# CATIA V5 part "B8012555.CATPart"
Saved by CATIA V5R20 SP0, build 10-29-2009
Part number: B8012555
Revision: 6
Definition: design
Nomenclature: B8012555
Source: made
Description: NOT SPECIFIED
Bounding box of the stored display mesh (mm): x -22.5 to 22.5, y -22.5 to 22.5, z 0 to 55
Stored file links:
  C:\Users\Utente\Desktop\3D files B801\B8012555.CATPart
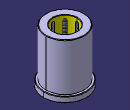
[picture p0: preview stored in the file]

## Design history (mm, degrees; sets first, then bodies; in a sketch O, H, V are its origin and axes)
Body1 "MANIFOLD_SOLID_BREP #38" (main body)
  Solid1: solid without history
Body2 "MANIFOLD_SOLID_BREP #76"
  Solid2: solid without history
Body3 "MANIFOLD_SOLID_BREP #114"
  Solid3: solid without history
Body4 "MANIFOLD_SOLID_BREP #152"
  Solid4: solid without history
Body5 "MANIFOLD_SOLID_BREP #190"
  Solid5: solid without history
Body6 "MANIFOLD_SOLID_BREP #228"
  Solid6: solid without history
Body7 "MANIFOLD_SOLID_BREP #266"
  Solid7: solid without history
Body8 "MANIFOLD_SOLID_BREP #304"
  Solid8: solid without history
Body9 "MANIFOLD_SOLID_BREP #342"
  Solid9: solid without history
Body10 "MANIFOLD_SOLID_BREP #2276"
  Solid10: solid without history
Body11 "MANIFOLD_SOLID_BREP #2314"
  Solid11: solid without history
Body12 "MANIFOLD_SOLID_BREP #2352"
  Solid12: solid without history
Body13 "MANIFOLD_SOLID_BREP #2390"
  Solid13: solid without history
Body14 "MANIFOLD_SOLID_BREP #2428"
  Solid14: solid without history
Body15 "MANIFOLD_SOLID_BREP #2466"
  Solid15: solid without history
Body16 "MANIFOLD_SOLID_BREP #2504"
  Solid16: solid without history
Body17 "MANIFOLD_SOLID_BREP #2542"
  Solid17: solid without history
Body18 "MANIFOLD_SOLID_BREP #2580"
  Solid18: solid without history
Body19 "MANIFOLD_SOLID_BREP #2618"
  Solid19: solid without history
Body20 "MANIFOLD_SOLID_BREP #2656"
  Solid20: solid without history
Body21 "MANIFOLD_SOLID_BREP #2694"
  Solid21: solid without history
Body22 "MANIFOLD_SOLID_BREP #2732"
  Solid22: solid without history
Body23 "MANIFOLD_SOLID_BREP #2770"
  Solid23: solid without history
Body24 "MANIFOLD_SOLID_BREP #2808"
  Solid24: solid without history
Body25 "MANIFOLD_SOLID_BREP #2846"
  Solid25: solid without history
Body26 "MANIFOLD_SOLID_BREP #2884"
  Solid26: solid without history
Body27 "MANIFOLD_SOLID_BREP #2922"
  Solid27: solid without history
Body28 "MANIFOLD_SOLID_BREP #2960"
  Solid28: solid without history
Body29 "MANIFOLD_SOLID_BREP #2998"
  Solid29: solid without history
Body30 "MANIFOLD_SOLID_BREP #3036"
  Solid30: solid without history
Body31 "MANIFOLD_SOLID_BREP #3074"
  Solid31: solid without history
Body32 "MANIFOLD_SOLID_BREP #3112"
  Solid32: solid without history
Body33 "MANIFOLD_SOLID_BREP #3150"
  Solid33: solid without history
Body34 "MANIFOLD_SOLID_BREP #3188"
  Solid34: solid without history
Body35 "MANIFOLD_SOLID_BREP #3226"
  Solid35: solid without history
Body36 "MANIFOLD_SOLID_BREP #3264"
  Solid36: solid without history
Body37 "MANIFOLD_SOLID_BREP #3302"
  Solid37: solid without history
Body38 "MANIFOLD_SOLID_BREP #3340"
  Solid38: solid without history
Body39 "MANIFOLD_SOLID_BREP #3378"
  Solid39: solid without history
Body40 "MANIFOLD_SOLID_BREP #3416"
  Solid40: solid without history
Body41 "MANIFOLD_SOLID_BREP #3454"
  Solid41: solid without history
Body42 "MANIFOLD_SOLID_BREP #3492"
  Solid42: solid without history
Body43 "MANIFOLD_SOLID_BREP #3530"
  Solid43: solid without history
Body44 "MANIFOLD_SOLID_BREP #3568"
  Solid44: solid without history
Body45 "MANIFOLD_SOLID_BREP #3606"
  Solid45: solid without history
Body46 "MANIFOLD_SOLID_BREP #3644"
  Solid46: solid without history
Body47 "MANIFOLD_SOLID_BREP #3682"
  Solid47: solid without history
Body48 "MANIFOLD_SOLID_BREP #3720"
  Solid48: solid without history
Body49 "MANIFOLD_SOLID_BREP #3758"
  Solid49: solid without history
Body50 "MANIFOLD_SOLID_BREP #3796"
  Solid50: solid without history
Body51 "MANIFOLD_SOLID_BREP #3834"
  Solid51: solid without history
Body52 "MANIFOLD_SOLID_BREP #3872"
  Solid52: solid without history
Body53 "MANIFOLD_SOLID_BREP #3910"
  Solid53: solid without history
Body54 "MANIFOLD_SOLID_BREP #3948"
  Solid54: solid without history
Body55 "MANIFOLD_SOLID_BREP #3986"
  Solid55: solid without history
Body56 "MANIFOLD_SOLID_BREP #4024"
  Solid56: solid without history
Body57 "MANIFOLD_SOLID_BREP #4062"
  Solid57: solid without history
Body58 "MANIFOLD_SOLID_BREP #4100"
  Solid58: solid without history
Body59 "MANIFOLD_SOLID_BREP #4138"
  Solid59: solid without history
Body60 "MANIFOLD_SOLID_BREP #4176"
  Solid60: solid without history
Body61 "MANIFOLD_SOLID_BREP #4214"
  Solid61: solid without history
Body62 "MANIFOLD_SOLID_BREP #4252"
  Solid62: solid without history
Body63 "MANIFOLD_SOLID_BREP #4290"
  Solid63: solid without history
Body64 "MANIFOLD_SOLID_BREP #4328"
  Solid64: solid without history
Body65 "MANIFOLD_SOLID_BREP #4366"
  Solid65: solid without history
Body66 "MANIFOLD_SOLID_BREP #4404"
  Solid66: solid without history
Body67 "MANIFOLD_SOLID_BREP #4442"
  Solid67: solid without history
Body68 "MANIFOLD_SOLID_BREP #4480"
  Solid68: solid without history
Body69 "MANIFOLD_SOLID_BREP #4518"
  Solid69: solid without history
Body70 "MANIFOLD_SOLID_BREP #4556"
  Solid70: solid without history
Body71 "MANIFOLD_SOLID_BREP #4594"
  Solid71: solid without history
Body72 "MANIFOLD_SOLID_BREP #4632"
  Solid72: solid without history
Body73 "MANIFOLD_SOLID_BREP #4670"
  Solid73: solid without history
Body74 "MANIFOLD_SOLID_BREP #4708"
  Solid74: solid without history
Body75 "MANIFOLD_SOLID_BREP #4746"
  Solid75: solid without history
Body76 "MANIFOLD_SOLID_BREP #4784"
  Solid76: solid without history
Body77 "MANIFOLD_SOLID_BREP #4822"
  Solid77: solid without history
Body78 "MANIFOLD_SOLID_BREP #4860"
  Solid78: solid without history
Body79 "MANIFOLD_SOLID_BREP #4898"
  Solid79: solid without history
Body80 "MANIFOLD_SOLID_BREP #4936"
  Solid80: solid without history
Body81 "MANIFOLD_SOLID_BREP #4974"
  Solid81: solid without history
Body82 "MANIFOLD_SOLID_BREP #5012"
  Solid82: solid without history
Body83 "MANIFOLD_SOLID_BREP #5050"
  Solid83: solid without history
Body84 "MANIFOLD_SOLID_BREP #5088"
  Solid84: solid without history
Body85 "MANIFOLD_SOLID_BREP #5126"
  Solid85: solid without history
Body86 "MANIFOLD_SOLID_BREP #5164"
  Solid86: solid without history
Body87 "MANIFOLD_SOLID_BREP #5202"
  Solid87: solid without history
Body88 "MANIFOLD_SOLID_BREP #5240"
  Solid88: solid without history
Body89 "MANIFOLD_SOLID_BREP #5278"
  Solid89: solid without history
Body90 "MANIFOLD_SOLID_BREP #5316"
  Solid90: solid without history
Body91 "MANIFOLD_SOLID_BREP #5354"
  Solid91: solid without history
Body92 "MANIFOLD_SOLID_BREP #5392"
  Solid92: solid without history
Body93 "MANIFOLD_SOLID_BREP #5430"
  Solid93: solid without history
Body94 "MANIFOLD_SOLID_BREP #5468"
  Solid94: solid without history
Body95 "MANIFOLD_SOLID_BREP #5506"
  Solid95: solid without history
Body96 "MANIFOLD_SOLID_BREP #5544"
  Solid96: solid without history
Body97 "MANIFOLD_SOLID_BREP #5582"
  Solid97: solid without history
Body98 "MANIFOLD_SOLID_BREP #5620"
  Solid98: solid without history
Body99 "MANIFOLD_SOLID_BREP #5658"
  Solid99: solid without history
Body100 "MANIFOLD_SOLID_BREP #5696"
  Solid100: solid without history
Body101 "MANIFOLD_SOLID_BREP #5734"
  Solid101: solid without history
Body102 "MANIFOLD_SOLID_BREP #5772"
  Solid102: solid without history
Body103 "MANIFOLD_SOLID_BREP #5810"
  Solid103: solid without history
Body104 "MANIFOLD_SOLID_BREP #5848"
  Solid104: solid without history
Body105 "MANIFOLD_SOLID_BREP #5886"
  Solid105: solid without history
Body106 "MANIFOLD_SOLID_BREP #5924"
  Solid106: solid without history
Body107 "MANIFOLD_SOLID_BREP #5962"
  Solid107: solid without history
Body108 "MANIFOLD_SOLID_BREP #6000"
  Solid108: solid without history
Body109 "MANIFOLD_SOLID_BREP #6038"
  Solid109: solid without history
Body110 "MANIFOLD_SOLID_BREP #6076"
  Solid110: solid without history
Body111 "MANIFOLD_SOLID_BREP #6114"
  Solid111: solid without history
Body112 "MANIFOLD_SOLID_BREP #6152"
  Solid112: solid without history
Body113 "MANIFOLD_SOLID_BREP #6190"
  Solid113: solid without history
Body114 "MANIFOLD_SOLID_BREP #6228"
  Solid114: solid without history
Body115 "MANIFOLD_SOLID_BREP #6266"
  Solid115: solid without history
Body116 "MANIFOLD_SOLID_BREP #6304"
  Solid116: solid without history
Body117 "MANIFOLD_SOLID_BREP #6342"
  Solid117: solid without history
Body118 "MANIFOLD_SOLID_BREP #6380"
  Solid118: solid without history
Body119 "MANIFOLD_SOLID_BREP #6418"
  Solid119: solid without history
Body120 "MANIFOLD_SOLID_BREP #6456"
  Solid120: solid without history
Body121 "MANIFOLD_SOLID_BREP #6494"
  Solid121: solid without history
